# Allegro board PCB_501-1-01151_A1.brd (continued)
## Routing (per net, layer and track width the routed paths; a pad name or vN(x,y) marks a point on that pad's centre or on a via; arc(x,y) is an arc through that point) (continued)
N20248573: length 1.7
  TOP w0.142: U4.A1 90.69,22.51 90.54,22.37 R34.1
N20257520: length 3.2
  TOP w0.142: U7.L9 87.64,38.01 R62.1
N20264538: length 18.6
  TOP w0.381: FB16.2 95.78,26.01 96.42,26.65 v1(97.52,26.65)
  BOTTOM w0.381: v1(97.52,26.65) J2.COM2 97.52,22.25 96.81,21.54 96.81,13.27 98.26,11.82 J2.COM1
N20269907: length 2.6
  TOP w0.142: R803.2 R17.2 57.02,59.46 56.85,59.63 U2.4
N20274074: length 3.3
  TOP w0.142: J8.5 6.61,38.96 FB5.1
N20274097: length 3.1
  TOP w0.142: J8.4 6.49,39.61 7.49,38.61 R173.1
N20280334: length 1.5
  TOP w0.142: D10.2 23.46,41.33 23.26,41.13 R176.2
N20280345: length 1.5
  TOP w0.142: R177.2 8.11,46.34 8.27,46.49 D11.2
N20323615: length 3.7
  BOTTOM w0.142: R133.1 R130.1 55.24,14.24 54.64,14.84 Y1.1
N20326291: length 3.5
  TOP w0.381: R116.2 14.35,34.24 J3.32
N20327026: length 1.4
  TOP w0.203: R109.2 32.78,11.95 D7.2
N20327568: length 5.8
  BOTTOM w0.381: R131.2 17.78,9.52 16.41,8.16 J3.28
N20327935: length 1.1
  TOP w0.142: R124.2 32.9,34.26 D8.2
N20368037: length 5.5
  TOP w0.142: J7.5 6.1,22.2 6.46,21.83 6.46,18.54 FB15.2
N20387129: length 4.1
  BOTTOM w0.142: SW6.5 73.88,16.38 73.9,16.4 R225.1
N20387131: length 8.3
  BOTTOM w0.142: R226.1 78.49,17.02 78.29,17.22 75.64,17.22 75.33,17.53 72.29,17.53 72.01,17.24 SW6.6
N20387133: length 11
  BOTTOM w0.142: R227.1 79.63,17.22 79.29,17.56 75.78,17.56 75.15,18.2 72.3,18.2 70.74,16.64 SW6.7
N20387143: length 13.9
  BOTTOM w0.142: R232.1 80.77,16.89 80.01,17.65 79.69,17.65 79.43,17.91 75.95,17.91 75.31,18.54 70.74,18.54 69.47,17.27 SW6.8
N20387145: length 4.8
  BOTTOM w0.142: SW7.4 91.95,32.13 93.73,30.35 R575.2
N20387147: length 2.9
  BOTTOM w0.142: SW7.3 93.22,32.38 94.11,31.5 R576.2
N20429331: length 3.5
  TOP w0.142: R771.1 92.18,86.47 92.25,86.4 U27.4 93.08,85.2 93.34,84.93 D28.1
N20436944: length 17.8
  BOTTOM w0.381: R121.2 15.46,21.6 J3.9 J3.10 18.49,17.78 J3.4 J3.3 J3.2 J3.1 12.46,17.81 J3.8
N20467513: length 4.5
  TOP w0.142: R579.1 R578.2 93.2,79.64 93.06,79.5 91.84,79.5 91.69,79.64 U26.5
N20496187: length 21.3
  TOP w0.381: R135.2 24.51,35.18 25.78,33.91 25.78,31.49 J3.26
  BOTTOM w0.381: J3.20 J3.19 J3.18 J3.17 18.49,28.22 J3.24 J3.25 J3.26
N20630241: length 5.5
  TOP w0.254: DA8.3 25.82,53 25.4,52.58 24.13,52.58 23.62,53.09 R782.2
N20681531: length 5.8
  TOP w0.142: v1(34.8,18.92) 35.14,18.59 35.37,18.59 C591.2 R810.1 v1(34.8,17.02)
  BOTTOM w0.142: R791.1 34.65,16.87 v1(34.8,17.02) ; v1(34.8,18.92) 34.14,19.58 R790.2
N20684634: length 6.1
  TOP w0.142: v1(35.19,13.42) 35.77,14.01 C592.2 R811.1 35.24,15.43 v1(34.8,15.88)
  BOTTOM w0.142: R793.1 34.7,12.93 v1(35.19,13.42) ; R792.2 34.56,15.64 v1(34.8,15.88)
N20685468: length 5.9
  TOP w0.142: v1(34.56,26.07) 35.19,25.43 R812.1 C593.2 35.21,24.29 v1(34.54,23.62)
  BOTTOM w0.142: v1(34.54,23.62) 34.44,23.73 R794.2 ; v1(34.56,26.07) 34.19,26.44 R795.1
N20685796: length 6.5
  TOP w0.142: v1(34.54,27.05) 35.08,27.05 35.41,27.39 R813.1 C594.2 35.41,29.64 35.08,29.97 v1(34.54,29.97)
  BOTTOM w0.142: R797.1 34.4,30.12 v1(34.54,29.97) ; R796.2 34.18,27.41 v1(34.54,27.05)
N20829804: length 1.3
  TOP w0.142: D29.1 13.52,69.48 13.51,69.47 R266.2
N20866761: length 3.6
  TOP w0.381: J3.33 22.73,34.34 R120.1
N20868982: length 4.5
  BOTTOM w0.381: R134.2 19.68,10.87 J3.29

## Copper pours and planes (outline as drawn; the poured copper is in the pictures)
5VIN on TOP: 22.48,92.33 23.11,91.69 23.11,88.01 24.13,87 24.13,83.57 23.62,83.06 22.61,83.06 22.35,82.8 22.35,82.42 22.31,82.38 21.17,82.38 21.13,82.35 17.6,82.35 17.4,82.55 17.4,92.33
GND on TOP: 27.97,43.59 32.79,43.59 34.5,41.88 34.5,41.36 34.42,41.27 31.37,41.27 31.24,41.4 31.24,41.78 30.73,42.29 28.83,42.29 28.7,42.16 28.7,41.4 28.58,41.27 27.69,41.27 27.05,41.91 27.05,42.67
GND on TOP: 78.87,58.67 78.49,58.29 78.49,56.9 79.12,56.26 79.88,56.26 80.01,56.39 80.01,58.13 80,58.13 79.46,58.67
GND on TOP: 38.35,63.25 39.5,63.25 39.5,62.48 39.37,62.36 38.61,62.36 38.23,62.74 38.23,63.12
GND on TOP: 36.83,60.58 39.37,60.58 39.37,61.21 38.35,61.21 38.23,61.34 38.23,61.47 37.72,61.98 36.96,61.98 36.58,61.6 36.58,60.83
GND on TOP: 77.34,58.29 75.56,58.29 75.18,57.91 75.18,56.77 75.69,56.26 77.34,56.26 77.47,56.39 77.47,58.17
GND on BOTTOM: 1.27,52.36 1.27,1.14 54.13,1.14 54.13,52.36 ; 41 cut-outs
GND on BOTTOM: 1.14,54.53 1.14,79.88 1.02,79.88 1.02,92.46 1.14,92.46 1.14,94.11 98.86,94.11 98.86,54.53 ; 19 cut-outs
GND on BOTTOM: 92.84,86.49 93.6,86.49 93.98,86.11 93.98,85.6 93.6,85.22 92.84,85.22 92.71,85.34 92.71,86.36
GND on BOTTOM: 82.91,79.41 83.26,79.05 83.26,78.57 82.98,78.29 82.15,78.29 81.97,78.47 81.97,79.38 81.99,79.41
GND on BOTTOM: 98.85,52.43 98.85,1.14 85.96,1.14 85.96,52.43 ; 8 cut-outs
GND on BOTTOM: 70.71,30.68 70.71,26.37 73.83,26.37 73.83,30.68
GND on L2_GND: 98.86,1.14 1.14,1.14 1.14,98.86 98.86,98.86 ; 2 cut-outs
GND on L3_SIG1, L4_SIG2: 1.02,79.88 1.02,92.46 8.13,92.46 8.13,79.88
GND on L5_PWR: 1.14,79.88 1.14,92.46 8.13,92.46 8.13,79.88
GND on L5_PWR: 1.14,1.14 1.14,44.25 59.87,44.25 60.32,44.7 63.5,44.7 64.01,45.21 64.01,47.12 65.53,48.64 66.44,48.64 70.89,53.09 86.61,53.09 86.74,52.96 90.81,52.96 95.38,48.39 95.38,44.25 98.86,44.25 98.86,1.14 ; 2 cut-outs
VBUS1_FL on BOTTOM: 92.58,85.98 92.58,84.84 92.07,84.84 91.31,85.6 91.19,85.6 90.68,86.11 90.68,86.74 90.81,86.87 91.69,86.87
VBUS2_FL on BOTTOM: 83.4,79.56 83.4,78.54 83.52,78.41 84.41,78.41 84.41,79.05 83.9,79.56
VBUS3_FL on BOTTOM: 60.96,81.15 60.96,80.37 61.04,80.29 61.04,79.29 61,79.25 61,78.34 61.06,78.28 62.27,78.28 62.27,79.11 62.15,79.22 62.15,80.94 61.94,81.15
VBUS4_FL on BOTTOM: 58.01,80.8 58.01,80.14 58.09,80.06 58.09,78.84 58.01,78.77 58.01,78.46 58.6,77.88 59.11,77.88 59.23,78 59.23,79.78 58.69,80.33 58.69,80.58 58.45,80.82 58.04,80.82
VDD_1V0 on TOP: 42.8,67.56 42.8,66.29 42.93,66.17 44.45,66.17 44.58,66.29 44.58,67.44 44.32,67.69 44.32,68.82 44.17,68.98 43.15,68.98 43.05,68.88 43.05,67.82
VDD_1V8 on TOP: 47.88,71.12 47.88,68.58 48.01,68.45 51.18,68.45 51.44,68.71 51.44,70.87 50.93,71.37 48.13,71.37
VDD_1V8 on L3_SIG1: 75.06,64.9 75.06,52.32 88.65,52.32 89.92,51.05 89.92,30.48 87.25,27.81 87.25,24.38 88.26,23.37 91.57,23.37 92.2,24 92.2,53.21 90.04,55.37 78.87,55.37 78.87,64.9
VDD_1V8 on L4_SIG2: 50.93,35.48 57.91,35.48 60.78,38.35 62.55,38.35 62.55,36.96 59.77,34.18 50.93,34.18
VDD_1V8 on L4_SIG2: 64.39,29.08 67.56,29.08 69.09,27.56 91.19,27.56 92.46,26.29 92.46,21.34 92.07,20.96 90.68,20.96 90.04,21.59 90.04,22.35 89.41,22.99 84.58,22.99 83.19,21.59 74.17,21.59 72.59,23.17 68.13,23.17 66.55,21.59 64.77,21.59 64.13,22.23 64.13,28.83
VDD_1V8 on L5_PWR: 46.3,71.63 76.84,71.63 77.72,70.74 77.72,61.98 77.34,61.6 55.24,61.6 54.61,62.23 54.61,65.81 51.84,68.58 46.1,68.58 46.1,71.42
VDD_1V8_SNS on TOP: 45.36,61.47 45.58,61.47 45.63,61.52 45.63,62.48 45.65,62.55 45.65,63.16 47.5,65 47.5,70.1 47.12,70.49 45.72,70.49 45.15,69.92 45.15,63.86 45.15,63.86 45.15,63.41 45.15,63.4 45.15,62.7 45.32,62.53 45.32,61.51
VDD_COINCELL_IN on BOTTOM: 16.26,75.56 17.91,75.56 18.16,75.31 18.16,73.66 17.27,73.66 16.26,74.68
VDD_DCDC6 on TOP: 39.37,68.83 39.75,68.45 39.75,66.93 39.88,66.8 41.47,66.8 41.69,66.58 41.69,65.45 41.51,65.28 39.88,65.28 39.5,65.66 37.97,65.66 37.72,65.91 37.72,68.33 38.23,68.83
VDD_DCJACK_5VIN on TOP: 8.76,81.79 9.02,81.53 16.38,81.53 16.89,82.04 16.89,91.62 16.44,92.07 9.12,92.07 8.76,91.72
VDD_DCJACK_5VIN on BOTTOM: 8.51,82.3 9.27,81.53 16.38,81.53 16.89,82.04 16.89,92.07 16.51,92.46 9.27,92.46 8.51,91.69
VDD_DCJACK_5VIN on L3_SIG1, L4_SIG2, L5_PWR: 8.76,81.79 9.02,81.53 16.38,81.53 16.89,82.04 16.89,92.07 16.51,92.46 9.02,92.46 8.76,92.2
VDD_EXT_LS_5V0 on TOP: 32.64,91.31 32.64,85.98 34.04,84.58 37.08,84.58 37.34,84.84 37.34,91.31 36.96,91.69 33.02,91.69
VDD_EXT_LS_5V0 on BOTTOM: 33.66,91.44 36.96,91.44 37.34,91.06 37.34,85.34 37.08,85.09 33.91,85.09 33.4,85.6 33.4,91.19
VDD_EXT_LS_5V0 on L5_PWR: 18.26,85.47 18.26,97.26 97.43,97.26 97.43,61.62 96.77,60.96 96.77,56.9 92.33,56.9 89.03,60.2 85.57,60.2 83.54,62.23 80.42,62.23 79.25,63.4 79.25,71.68 78.28,72.64 47.02,72.64 46.08,73.58 46.08,84.73 45.34,85.47
VDD_EXT_LS_5V0_SNS on TOP: 32.89,83.82 33.91,83.82 34.16,84.07 36.7,84.07 37.21,83.57 37.21,80.52 36.96,80.26 32.64,80.26 32.26,80.65 32.26,82.55 32.38,82.68 32.51,82.68 32.64,82.8 32.64,83.57
VDD_HIGH_CAP on L5_PWR: 63.37,47.12 63.37,45.34 63.12,45.09 62.1,45.09 61.72,45.47 61.72,45.85 61.21,46.35 55.63,46.35 55.5,46.48 55.5,47.24 55.75,47.5 62.99,47.5
VDD_HIGH_IN_3V3 on TOP: 46.6,58.45 48.4,58.45 48.59,58.27 48.62,58.23 49.01,58.23 49.09,58.15 49.09,57.77 48.98,57.66 48.52,57.66 47.97,58.21 46.61,58.21 46.6,58.22
VDD_HIGH_IN_3V3 on TOP: 39.88,46.99 40.39,46.48 40.39,42.55 36.83,38.99 34.29,38.99 33.63,39.64 30.59,39.64 30.48,39.75 30.48,40.89 30.35,41.02 29.84,41.02 29.84,41.4 29.97,41.53 30.73,41.53 30.86,41.4 30.86,41.15 30.99,41.02 34.36,41.02 36.58,43.23 36.58,45.59 36.2,45.97 35.05,45.97 34.34,46.69 34.34,47.96 33.4,48.9 30.86,48.9 28.19,51.56 28.19,59.56 28.58,59.94 29.84,59.94 30.35,59.44 30.35,53.59 31.62,52.32 33.35,52.32 35.92,49.76 35.92,48.29 37.21,46.99
VDD_HIGH_IN_3V3 on TOP: 39.59,59.28 39.83,59.28 39.99,59.11 40.25,59.11 40.52,58.84 41.52,58.84 41.53,58.83 41.53,58.63 41.52,58.63 40.41,58.63 40.26,58.77 40.1,58.77 40.1,58.77 39.57,58.77 39.47,58.87 39.47,59.17
VDD_HIGH_IN_3V3 on L3_SIG1: 39.24,57.66 39.5,57.4 48.77,57.4 52.83,61.47 52.83,67.18 51.82,68.2 45.34,68.2 39.88,62.74 28.32,62.74 27.43,61.85 27.43,58.42 28.19,57.66 ; 1 cut-out
VDD_HIGH_IN_3V3 on L4_SIG2: 54.61,44.96 56.77,44.96 57.02,45.21 57.02,45.85 56.77,46.1 56.01,46.1 55.88,45.97 50.67,45.97 49.91,46.74 42.55,46.74 41.4,45.59 37.72,45.59 37.47,45.34 37.47,40.13 35.56,38.23 35.56,20.32 42.86,13.02 59.63,13.02 62.79,9.86 86.18,9.86 89.92,13.59 89.92,21.97 89.28,22.61 85.47,22.61 84.91,22.05 84.91,16.08 82.17,13.34 66.27,13.34 62,17.6 46.66,17.6 39.12,25.15 39.12,37.08 40.39,38.35 40.39,42.55 43.05,45.21 49.66,45.21 50.04,44.83 54.48,44.83
VDD_HIGH_IN_3V3 on L5_PWR: 36.96,45.47 39.86,45.47 39.86,38.99 30.48,38.99 30.48,42.67 36.2,42.67 36.58,43.05 36.58,45.09
VDD_HIGH_IN_3V3_SNS on TOP: 41.4,50.55 40.26,49.4 40.26,47.62 40.13,47.5 37.47,47.5 37.34,47.62 37.34,52.2 37.97,52.83 41.15,52.83 41.4,52.58
VDD_HUB_LED on BOTTOM: 34.36,98.4 88.99,98.4 89.15,98.24 89.15,96.39 89.03,96.27 34.16,96.27 33.91,96.52 33.91,97.95
VDD_LDO1 on TOP: 46.61,58.04 47.94,58.04 48.44,57.54 51.82,57.54 52.44,58.17 53.34,58.17 53.34,56.77 53.21,56.64 52.32,56.64 52.07,56.9 50.16,56.9 50.09,56.82 48.61,56.82 47.61,57.82 46.61,57.82 46.6,57.83 46.6,58.02
VDD_LDO_2V8 on TOP: 54.36,59.44 55.5,59.44 55.75,59.18 55.75,55.75 55.5,55.5 54.23,55.5 53.85,55.88 53.85,58.93
VDD_LDO_2V8 on L4_SIG2: 94.23,55.5 95.57,54.17 95.57,50.61 96.39,49.78 96.39,13.97 89.81,7.39 79.45,7.39 79.45,9.37 86.59,9.37 92.96,15.75 92.96,46.86 87.76,52.07 64.77,52.07 59.44,57.4 54.61,57.4 54.1,57.91 54.1,59.18 54.99,60.07 62.87,60.07 66.68,56.26 77.85,56.26 78.74,55.37 85.98,55.37 86.11,55.5
VDD_NVCC_3V3 on TOP: 41.52,59.24 40.79,59.24 40.78,59.25 40.7,59.25 40.7,59.35 40.44,59.61 40.42,59.61 39.7,60.33 36.2,60.33 36.07,60.2 36.07,59.8 36.2,59.66 39.64,59.66 40,59.3 40.21,59.3 40.49,59.03 40.49,59.03 41.53,59.03 41.53,59.24
VDD_NVCC_3V3 on L4_SIG2: 20.45,46.74 19.3,47.88 19.3,49.78 22.48,49.78 22.48,56.9 26.29,60.71 37.85,60.71 37.85,56.77 27.3,56.77 25.53,54.99 25.53,49.78 26.92,49.78 27.18,49.53 27.18,48.77 25.15,46.74
VDD_NVCC_3V3 on L5_PWR: 57.15,38.99 57.15,45.59 56.9,45.85 48.39,45.85 46.61,47.62 33.66,47.62 30.23,51.05 23.75,51.05 22.73,50.04 22.73,46.23 25.15,43.81 34.04,43.81 36.07,45.85 40.64,45.85 40.77,45.72 40.77,38.34 48.93,38.42 50.38,39.87 55.7,39.87 56.28,39.29 56.28,38.84 56.41,38.71 56.87,38.71
VDD_NVCC_SD1 on TOP: 90.93,23.75 92.33,23.75 93.73,25.15 93.73,30.91 91.87,32.77 85.85,32.77 85.34,32.26 85.34,31.24 85.6,30.99 91.69,30.99 92.46,30.23 92.46,28.7 92.07,28.32 92.07,26.8 92.46,26.42 92.46,25.27 92.07,24.89 90.93,24.89
VDD_NVCC_SD1 on BOTTOM: 65.79,35.31 66.17,35.31 66.68,35.81 74.04,35.81 76.84,33.02 78.61,33.02 79.38,32.26 85.72,32.26 86.11,31.88 86.11,30.47 83.7,30.47 83.06,31.12 76.58,31.12 73.79,33.91 65.79,33.91 64.64,35.05 64.64,35.18 64.77,35.31 65.66,35.31 65.79,35.18
VDD_PERI_3V3 on TOP: 37.62,9.02 37.62,11.2 38.48,12.07 44.96,12.07 45.34,11.68 45.34,11.05 47.73,11.05 49.53,12.85 49.53,17.14 49.66,17.27 51.44,17.27 51.56,17.4 51.56,18.03 51.31,18.29 49.91,18.29 49.66,18.03 48.51,18.03 48.51,18.8 49.15,19.43 51.94,19.43 53.09,20.57 53.09,26.03 53.85,26.8 54.99,26.8 55.24,26.54 55.24,13.97 54.23,12.95 54.23,10.41 53.72,9.91 51.33,9.91 49.71,8.28 38.35,8.28
VDD_PERI_3V3 on TOP: 28.7,41.15 27.18,41.15 26.92,40.89 26.92,38.99 27.18,38.73 28.7,38.73 28.96,38.99 28.96,39.75 29.21,40.01 29.21,40.89 29.34,41.02 29.59,41.02 29.72,41.15 29.72,41.4 29.59,41.53 29.08,41.53
VDD_PERI_3V3 on TOP: 80.14,61.47 80.14,58.65 80.31,58.47 80.31,56.47 80.39,56.39 81.79,56.39 82.55,57.15 82.55,60.96 81.79,61.72 80.39,61.72
VDD_PERI_3V3 on L3_SIG1: 7.11,47.7 7.11,36.91 8.2,35.81 21.21,35.81 22.73,37.34 22.73,39.12 23.5,39.88 27.3,39.88 28.45,38.73 32.26,38.73 34.04,40.51 34.04,45.59 31.75,47.88 28.45,47.88 26.54,45.97 21.84,45.97 20.45,47.37 18.92,47.37 15.24,43.69 10.16,43.69 9.65,44.2 9.65,47.62 9.32,47.96 7.37,47.96
VDD_PERI_3V3 on L3_SIG1: 15.88,14.86 25.53,14.86 26.16,15.49 26.16,21.21 25.27,22.1 19.05,22.1 18.67,22.48 18.67,24.77 19.43,25.53 31.24,25.53 32,26.29 32,30.73 35.05,33.78 39.24,33.78 39.88,34.42 41.58,34.42 41.81,34.19 41.81,33.45 39.53,33.45 39.53,22.31 42.46,22.31 44.32,20.45 44.32,18.97 41.4,16.05 41.4,9.14 40.77,8.51 33.27,8.51 32.51,9.27 32.51,11.68 31.37,12.83 23.37,12.83 21.59,11.05 15.82,11.05 15.49,11.38 15.49,14.48
VDD_PERI_3V3 on L3_SIG1: 32.13,72.01 30.35,72.01 29.21,73.15 15.88,73.15 15.16,72.44 15.16,70.61 26.29,70.61 29.21,67.69 33.15,67.69 33.53,68.07 33.53,70.61
VDD_PERI_3V3 on L3_SIG1: 54.28,1.14 51.66,3.76 51.66,20.24 52.32,20.9 52.32,24.64 54.48,26.8 55.91,26.8 57.02,25.68 57.02,20.07 59.18,17.91 61.98,17.91 62.1,18.03 64.39,18.03 65.28,17.14 65.28,14.48 64.01,13.21 55.5,13.21 53.98,11.68 53.98,7.75 55.88,5.84 57.53,5.84 57.53,5.85 78.28,5.85 82.3,9.87 82.3,15.37 79.5,18.16 79.5,23.11 78.99,23.62 76.33,23.62 76.2,23.75 76.2,26.29 76.33,26.42 84.58,26.42 85.09,25.91 85.09,19.56 85.72,18.92 91.82,18.92 93.41,20.51 93.41,56.77 83.69,56.77 82.93,56.01 80.39,56.01 79.88,56.52 79.88,65.02 80.52,65.66 89.66,65.66 93.73,69.72 93.73,87.27 87.91,93.09 85.17,93.09 84.84,93.42 84.84,96.01 85.09,96.27 91.31,96.27 96.77,90.81 96.77,16.76 95.94,15.93 87.12,15.93 85.85,14.66 85.85,5.62 81.38,1.14
VDD_PERI_3V3 on L4_SIG2: 41.4,34.42 49.78,34.42 51.56,32.64 51.56,28.45 50.93,27.81 42.16,27.81 40.89,29.08 40.89,33.91
VDD_PERI_3V3 on L4_SIG2: 20.07,41.66 34.36,41.66 35.27,40.75 35.27,30.48 32.57,30.48 32.57,35.37 32.58,35.37 32.58,36.9 33.02,37.34 33.02,37.97 32.64,38.35 29.34,38.35 27.3,36.32 20.32,36.32 19.43,37.21 19.43,41.02
VDD_PERI_3V3 on L5_PWR: 16.71,79.06 2.96,79.06 2.16,78.26 2.16,44.65 2.24,44.58 6.35,44.58 6.86,44.07 6.86,32.26 8,31.12 10.54,31.12 12.07,32.64 23.24,32.64 25.27,34.67 25.27,37.11 26.8,38.63 28.73,38.63 29.49,39.4 29.49,42.47 28.78,43.18 24.77,43.18 22.48,45.47 22.48,49.15 20.19,51.44 17.91,51.44 17.08,52.26 17.08,57.21 17.14,57.28 17.14,78.62
VDD_PERI_FIL_3V3 on TOP: 78.99,61.85 75.82,61.85 75.31,61.34 75.31,59.44 75.95,58.8 77.72,58.8 77.98,59.05 79.12,59.05 79.12,61.72
VDD_PERI_FIL_3V3 on BOTTOM: 74.32,65.28 75.06,66.01 75.06,69.98 75.18,70.1 75.18,72.9 74.8,73.28 74.8,73.91 74.55,74.17 73.03,74.17 72.77,73.91 72.77,73.53 72.64,73.41 67.56,73.41 66.68,74.29 66.68,77.47 67.31,78.1 78.36,78.1 81.22,75.25 81.22,63.31 75.56,57.66 65.15,57.66 59.69,63.12 59.69,72.52 60.45,73.28 65.41,73.28 66.55,72.14 66.55,65.66 66.93,65.28
VDD_PMIC_LS_5V0 on TOP: 31.12,58.29 31.12,53.85 31.5,53.47 32.51,53.47 32.89,53.85 32.89,56.01 32.64,56.26 32.64,58.04 32.38,58.29
VDD_PMIC_LS_5V0 on TOP: 58.8,57.91 59.05,57.66 59.94,57.66 60.2,57.91 60.2,59.44 60.07,59.56 58.93,59.56 58.8,59.44
VDD_PMIC_LS_5V0 on BOTTOM: 88.14,60.96 89.03,60.96 89.15,60.83 89.15,59.56 90.04,58.67 90.04,56.39 88.52,56.39 87.88,57.02 87.88,60.71
VDD_PMIC_LS_5V0 on BOTTOM: 33.02,90.68 33.02,87.38 32,87.38 31.62,87.76 29.34,87.76 25.53,83.95 25.53,69.98 33.15,62.36 33.15,54.86 32.51,54.23 30.86,54.23 30.23,54.86 30.23,60.83 23.24,67.82 23.24,87 26.92,90.68
VDD_PMIC_LS_5V0 on L5_PWR: 30.18,56.8 32.99,56.8 36.07,53.72 46.86,53.72 50.55,57.4 53.47,57.4 56.39,60.32 84.2,60.32 85.09,59.44 88.39,59.44 89.66,58.17 89.66,53.34 71.12,53.34 67.82,50.04 67.56,50.04 66.42,48.9 59.94,48.9 58.55,50.29 53.47,50.29 51.94,48.77 49.4,48.77 48.77,49.4 46.99,49.4 46.99,49.28 45.85,48.13 33.66,48.13 29.84,51.94 29.84,56.46
VDD_PMIC_LS_5V0_SNS on TOP: 48.51,59.94 51.44,59.94 51.94,59.44 51.94,58.04 51.73,57.83 50.12,57.83 49.78,58.17 49.78,58.93 49.66,59.05 48.21,59.05 48.18,59.03 46.61,59.03 46.61,59.23 47.8,59.23
VDD_PMIC_LS_5V0_SNS on TOP: 40.39,58.04 41.53,58.04 41.53,57.79 41.01,57.79 40.96,57.74 40.67,57.74 40.6,57.66 40.6,57.57 39.54,56.52 33.15,56.52 33.15,58.04 34.54,58.04 34.67,57.91 37.21,57.91 37.34,57.79 40.13,57.79
VDD_PMIC_LS_5V0_SNS on BOTTOM: 34.54,57.91 36.32,57.91 36.7,57.53 36.7,54.99 40.26,51.44 47.5,51.44 50.8,54.74 50.8,57.4 50.55,57.66 50.55,58.55 50.67,58.67 51.69,58.67 52.2,58.17 52.2,52.7 49.53,50.04 45.85,50.04 45.4,49.59 37.53,49.59 34.29,52.83 34.29,57.66
VDD_SNVS_IN on TOP: 36.32,45.47 36.32,43.18 36.2,43.05 33.91,43.05 33.4,43.56 33.4,44.83 34.29,45.72 36.07,45.72
VDD_SNVS_IN on TOP: 35.94,68.96 37.21,68.96 37.47,68.71 37.47,67.44 37.59,67.31 37.59,66.29 37.47,66.17 35.81,66.17 35.69,66.29 35.69,68.71
VDD_SNVS_IN on L3_SIG1: 19.05,69.34 23.9,69.34 26.42,66.83 34.06,66.83 39.12,71.88 55.88,71.88 57.15,70.61 57.15,64.64 58.42,63.37 58.42,61.34 58.17,61.09 54.61,61.09 53.47,62.23 53.47,67.94 52.7,68.71 45.09,68.71 40.26,63.88 19.43,63.88 18.41,64.9 18.41,68.71
VDD_SNVS_IN on L4_SIG2: 37.08,45.59 37.47,45.97 40.77,45.97 41.91,47.12 48.51,47.12 48.77,47.37 53.34,47.37 53.72,46.99 56.01,46.99 57.15,45.85 57.53,45.85 57.79,46.1 57.79,46.99 55.6,49.17 55.24,49.15 43.31,49.15 42.29,48.13 36.05,48.13 35.05,47.13 34.18,47.13 32.04,44.99 11.78,44.99 9.65,47.12 9.65,60.13 13.53,64.01 22.23,64.01 25.4,67.18 25.4,72.14 20.57,76.96 15.11,76.96 6.98,68.83 6.98,47.88 6.1,46.99 6.1,41.27 8.26,39.12 15.85,39.12 18.65,41.91 36.2,41.91 37.08,42.8
VDD_SOC_ARM_IN on TOP: 52.45,48.01 52.45,45.97 51.94,45.47 49.66,45.47 49.28,45.85 49.28,46.61 49.78,47.12 49.78,48.51 49.91,48.64 51.82,48.64
VDD_SOC_ARM_IN on BOTTOM: 59.05,40.01 60.66,40.01 60.89,40.23 60.89,43.05 61.16,43.33 61.16,43.74 60.83,44.07 59.31,44.07 58.8,43.56 52.35,43.56 51.86,44.04 51.86,45.89 52.45,46.48 52.45,47.24 49.66,47.24 49.53,47.12 49.53,44.07 49.91,43.69 49.91,41.78 50.04,41.66 56.77,41.66 57.79,40.64 58.42,40.64
VDD_SOC_ARM_IN_SNS on TOP: 49.53,49.02 49.53,51.94 49.59,52 49.59,52.8 49.45,52.94 47.41,52.94 47.01,52.55 47.01,47.83 47.71,47.13 49.28,47.13 49.28,48.77
VDD_SOC_CAP on L3_SIG1: 57.91,44.45 61.6,44.45 61.98,44.07 61.98,39.88 61.6,39.5 58.04,39.5 57.91,39.62
VIN_PMIC_5V0 on TOP: 48.08,58.87 48.08,58.88 48.28,58.88 48.34,58.94 49.56,58.94 49.66,58.84 49.66,58.49 49.52,58.36 48.65,58.36 48.38,58.63 46.61,58.63 46.61,58.87
VIN_PMIC_5V0 on TOP: 40.24,58.16 40.62,58.16 40.68,58.21 41.54,58.21 41.54,58.45 40.67,58.45 40.57,58.55 40.34,58.55 40.25,58.63 39.42,58.63 39.36,58.7 39.36,59.15 39.18,59.33 38.87,59.33 38.86,59.32 38.49,59.32 38.35,59.18 38.35,58.17 38.6,57.92 40,57.92
VIN_PMIC_5V0 on TOP: 30.35,76.07 27.56,76.07 26.8,75.31 16.51,75.31 16,75.82 16,79.76 16.13,79.88 19.3,79.88 19.56,80.14 19.56,81.41 20.27,82.12 24.43,82.12 24.77,81.79 27.3,81.79 28.96,83.44 30.86,83.44 30.99,83.57 31.62,83.57 31.62,82.68 32,82.68 32,77.72
VIN_PMIC_5V0 on TOP: 45.09,54.1 45.09,54.84 44.41,55.52 44.41,55.56 44.37,55.6 44.37,56.39 44.37,56.39 44.16,56.39 44.16,55.48 44.16,54.69 44.75,54.1
VIN_PMIC_5V0 on TOP: 40.67,56.9 41.53,56.9 41.66,56.77 41.66,56.64 41.78,56.52 41.91,56.52 41.97,56.46 41.97,55.52 41.82,55.38 40.77,55.38 40.51,55.12 40.01,55.12 39.88,55.24 39.88,55.78 40.65,56.56 40.65,56.88
VIN_PMIC_5V0 on TOP: 46.61,61.02 48.01,61.02 48.06,61.07 48.72,61.07 48.9,61.24 48.9,61.6 48.8,61.69 48.8,61.69 48.7,61.79 47.67,61.79 47.58,61.69 47.58,61.69 47.49,61.6 47.48,61.6 47.14,61.26 46.6,61.26 46.6,61.03
VIN_PMIC_5V0 on TOP: 46.61,56.87 47.58,56.87 48,56.45 48,56.08 47.88,55.96 46.97,55.96 46.82,56.11 46.82,56.34 46.56,56.6 46.56,56.82
VIN_PMIC_5V0 on BOTTOM: 39.85,56.86 39.21,57.5 38.38,57.5 38.23,57.66 38.23,59.31 38.27,59.35 40.29,59.35 40.29,59.33 40.81,58.82 41.8,58.82 42.06,58.56 42.06,56 42.73,55.32 44.43,55.32 44.86,55.75 46.31,55.75 46.46,55.9 46.46,56.37 47.12,57.02 48.26,57.02 48.51,57.28 48.51,58.55 48.13,58.55 47.88,58.8 47.88,60.32 47.62,60.58 46.74,60.58 46.48,60.83 46.48,62.23 46.86,62.61 48.39,62.61 49.15,61.85 49.15,59.31 49.28,59.18 49.91,59.18 50.16,58.93 50.16,54.86 47.5,52.2 40.51,52.2 39.85,52.86
VIN_PMIC_5V0 on L5_PWR: 18.92,83.94 18.92,52.15 19.51,51.56 28.19,51.56 28.58,51.94 28.58,56.38 29.85,57.66 33.21,57.66 36.9,53.98 44.96,53.98 45.34,54.36 46.48,54.36 50.29,58.17 53.34,58.17 54.23,59.05 54.23,64.9 52.07,67.06 44.58,67.06 44.58,82.72 42.9,84.39 19.38,84.39 ; 1 cut-out
(no net) on TOP: 1.14,1.14 1.14,30.18 4.19,30.18 4.19,35.46 1.14,35.46 1.14,65.58 17.83,65.58 17.83,33.02 85.45,33.02 85.45,66.34 1.17,66.34 1.17,79.88 1.14,79.88 1.14,92.46 1.17,92.46 1.17,98.86 34.67,98.86 34.67,96.22 34.51,96.2 34.36,96.24 34.26,96.23 34.21,96.14 34.21,95.76 34.4,95.57 34.67,95.57 34.67,95.89 91.69,95.89 91.69,98.86 98.86,98.86 98.86,32.98 98.82,20.73 98.77,1.14 ; 87 cut-outs
DCDC1_L1 on TOP: 46.1,55.24 46.1,56.39 46.52,56.39 46.52,56.07 46.92,55.67 48.22,55.67 49.48,54.41 49.48,53.67 49.27,53.47 47.5,53.47 47.12,53.85 47.12,54.23
DCDC2_L2 on TOP: 43.38,54.28 43,53.9 43,52.76 43.31,52.45 45.34,52.45 45.59,52.7 45.59,53.59 45.34,53.84 44.8,53.84 44.02,54.62 44.02,55.51 43.97,55.56 43.97,56.4 43.76,56.4 43.76,55.54 43.38,55.15
DCDC3_L3 on TOP: 42.16,55.46 41.97,55.26 40.89,55.26 40.63,55 40.13,55 40.13,55 39.12,55 38.86,54.74 38.86,53.59 39.12,53.34 40.98,53.34 41.62,53.98 41.62,54 42.48,54.86 42.48,55.38 42.39,55.47 42.39,56.39 42.16,56.39
DCDC4_L4A on TOP: 46.16,61.47 46.68,61.47 46.69,61.47 47.1,61.47 47.53,61.9 49.58,61.9 49.58,61.9 49.75,61.9 49.91,62.06 49.91,62.74 49.78,62.87 48.39,62.87 47.73,62.87 47.21,62.34 46.16,62.34 46.16,62.34
DCDC4_L4B on TOP: 45.76,61.46 45.97,61.46 45.97,61.46 45.97,62.39 46.13,62.5 46.83,62.5 47.87,63.55 49.7,63.55 49.86,63.71 49.86,64.44 49.77,64.53 48.84,64.53 48.84,64.52 47.25,64.52 47.24,64.52 47.12,64.52 45.74,63.14 45.74,62.85 45.73,62.81 45.73,61.5
DCDC5_L5 on TOP: 44.45,64.33 43.8,64.33 43.61,64.14 43.61,62.92 43.57,62.88 43.57,61.47 43.37,61.47 43.33,61.51 43.33,62.98 42.7,63.61 42.7,65.44 42.91,65.66 44.45,65.66 44.58,65.53 44.58,64.46
DCDC6_L6 on TOP: 42.16,61.47 42.16,62.36 42.04,62.48 41.15,62.48 40.32,63.32 39.94,63.32 39.76,63.5 39.76,64.78 39.88,64.9 41.53,64.9 41.58,64.85 41.58,63.58 42.42,62.74 42.42,61.47
INT_LDO on TOP: 40.36,57.24 41.52,57.24 41.53,57.23 41.53,57.03 41.51,57 40.62,57 39.09,55.48 38.1,55.48 38.03,55.55 38.03,56.14 38.21,56.32 39.43,56.32
NVCC_DRAM_1V35 on TOP: 46.99,45.21 46.99,43.85 46.32,43.18 43.43,43.18 42.93,43.69 42.93,45.47 43.31,45.85 46.35,45.85
NVCC_DRAM_1V35 on BOTTOM: 62.74,44.83 64.39,44.83 65.15,44.07 66.68,44.07 66.8,43.94 66.8,41.53 67.18,41.15 68.07,41.15 68.2,41.02 68.2,40.26 67.94,40.01 65.66,40.01 65.02,39.37 62.74,39.37 62.61,39.5 62.61,44.7
NVCC_DRAM_1V35 on L4_SIG2: 42.42,44.07 42.42,40.01 43.43,38.99 51.69,38.99 52.2,39.5 70.1,39.5 77.34,32.26 86.61,32.26 88.39,34.04 88.39,45.59 85.98,48.01 74.17,48.01 71.88,45.72 57.79,45.72 56.52,44.45 46.23,44.45 45.85,44.83 43.18,44.83
NVCC_DRAM_1V35_SNS on TOP: 44.96,49.78 45.85,50.67 45.85,51.82 45.59,52.07 43.56,52.07 42.93,51.44 42.93,46.6 43.18,46.35 44.7,46.35 44.96,46.61
NVCC_LCD on TOP: 67.31,15.88 72.9,15.88 74.04,17.02 81.66,17.02 82.55,16.13 82.55,11.18 78.74,7.37 66.73,7.37 66.34,7.75 66.34,14.91 ; 2 cut-outs
NVCC_LCD on L4_SIG2: 44.83,22.61 47.88,22.61 48.26,22.23 48.26,21.72 47.88,21.34 47.88,21.08 48.26,20.7 50.8,20.7 51.31,21.21 59.94,21.21 59.94,18.23 57.33,18.23 57.33,19.32 57.22,19.43 46.61,19.43 44.7,21.34 44.7,22.48
NVCC_LCD on L5_PWR: 55.88,38.48 57.66,38.48 57.66,34.54 57.4,34.29 57.4,22.65 59.62,20.43 59.62,17.04 60.32,16.34 68.58,16.34 68.58,13.7 60.49,13.7 58.2,15.99 58.2,19.53 55.88,21.85
PFBIN on TOP: 46.61,32.26 41.15,32.26 38.1,29.21 38.1,25.02 35.81,22.73 35.81,18.8 42.04,12.57 45.97,12.57 46.1,12.45 46.1,11.43 47.24,11.43 47.37,11.56 47.37,13.84 47.12,14.1 43.56,14.1 40.77,16.89 40.77,19.81 41.02,20.07 42.55,20.07 43.05,20.57 43.05,23.11 42.29,23.88 42.29,29.08 43.87,30.66 46.02,30.66 46.99,31.62 46.99,31.88
PMIC_CC on TOP: 40.6,61.01 41.52,61.01 41.54,61.03 41.54,61.27 41.51,61.31 40.79,61.31 40.55,61.55 40.55,61.94 40.26,62.23 38.35,62.23 37.97,62.61 37.97,63.37 37.85,63.5 35.31,63.5 35.18,63.37 35.18,62.48 35.56,62.1 37.74,62.1 38.36,61.48 39.89,61.48 39.98,61.38 40.23,61.38
SYS_BU on TOP: 39.72,63.2 40.27,63.2 40.42,63.06 40.42,62.7 40.78,62.35 41.97,62.35 42,62.31 42,61.48 41.95,61.43 41.26,61.43 40.22,62.47 39.84,62.47 39.72,62.59

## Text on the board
Ref Des/Assembly Bottom: ASSEMBLY BOT | SHEET 3 OF 3 | LAYER: | REV:A1 | TIXU_MX6Y_Main_Board | 701-1-01380 | DESIGNED FOR: TIXU_MX6Y | PART NO: | PARTNAME: | TOLERANCE + / - 0.1MM | ALL DIMENSIONS ARE IN MM
Package Geometry/Pastemask Bottom: "FIDUCIAL'S  WILL NOT BE THRU OPEN, IT SHOULD BE HALFETCH". | PASTE BOTTOM
Ref Des/Silkscreen Bottom: A | C | D | B | SW6 | 1V35 | 0 | 1 | eMMC | SD | QSPI | P3 | BOOT DEV | P1 | P2 | RESERVED | INTERNAL | SERIAL | P0 | FUSE | ON | BOOT TYPE
User.Comments: PARTNAME: | PART NO: | DESIGNED FOR: TIXU_MX6Y | 501-1-01151 | TIXU_MX6Y_Main_Board | REV:A1 | LAYER: | ALL DIMENSIONS ARE IN MM | TOLERANCE + / - 0.1MM
TOP: L1_TOP
Package Geometry/Pastemask Top: "FIDUCIAL'S  WILL NOT BE THRU OPEN, IT SHOULD BE HALFETCH".
Ref Des/Silkscreen Top: OVP | POR | TX | NVCC_3 | SNVS | PB | PA | P/N:501-1-01151_A1 | SOC | 1V | PG | 2V8 | JTAG | RX | GPIO | 5VIN | H3V3 | 1V8 | BOOT | ON/OFF | RESET | USER_1 | PMIC_PB | USER_2 | USER | P5 | P4 | P3 | P2 | P1 | R
DIMENSION: PARTNAME: | PART NO: | DESIGNED FOR: TIXU_MX6Y | 701-1-01380 | TIXU_MX6Y_Main_Board | REV:A1 | LAYER: | SHEET 2 OF 3 | ASSEMBLY TOP | ALL DIMENSIONS ARE IN MM | TOLERANCE + / - 0.1MM
User.6: T*
User.9: PANEL FIDUCIAL | (TOP AND BOTTOM) | (3 PLACES) | TOOLING HOLES 3.20 MM | (4 PLACES) | MOUSE BITE DETAIL
User.20: PANEL DRAWING BOT | SHEET 3 OF 3 | LAYER: | REV:A1 | TIXU_MX6Y_Main_Board | 501-1-01151 | DESIGNED FOR: TIXU_MX6Y | PART NO: | PARTNAME: | TOLERANCE + / - 0.1MM | ALL DIMENSIONS ARE IN MM
User.21: PARTNAME: | PART NO: | DESIGNED FOR: TIXU_MX6Y | 501-1-01151 | TIXU_MX6Y_Main_Board | REV:A1 | LAYER: | PANEL ART | ALL DIMENSIONS ARE IN MM | TOLERANCE + / - 0.1MM
User.22: DO NOT SCALE DRAWING PRINT | SHEET 1 OF 3 | IMPEDANCE REQUIREMENT | IMPEDANCE TABLE | IMX_6ULL_EVALUATION BOARD
User.23: PMT_ | PMB_ | PNP_ | 501-1-01151_A1 | .ART -  BOTTOM PASTE | .XLS -  PICK AND PLACE DATA | PCB Thickness 1.6 mm | 10) ALL COMPONENT AND MATERIAL USED ARE PB FREE AND ROHS COMPLAINT. | 4) SOLDER PASTE TOOLING SHOULD BE MADE USING PMB_501-1-01151_A1.ART FOR SECONDARY SIDE. | 9) RED COLOR HIGHLIGHTED COMPONENTS ARE NO MOUNT.
User.24: SHEET 1 OF 3 | INITIAL RELEASE
User.25: LAYER STACKUP DETAILS | SOLDER MASK | L1_TOP Cu, 1oz include Plating | 3.66  mil PREPEG | 4 mil, CORE\PREPEG | L2_GND Cu, 1oz | L3_SIG1 Cu, 1oz | 39mil, CORE\PREPEG | L4_SIG2 Cu, 1oz | L5_PWR Cu, 1oz | 3.66 mil PREPEG | L6_BOTTOM Cu, 1oz include Plating | 63 MILS | TOL. +\- 10% | LAYER NAME | L6_BOT | L1_TOP | L3_SIG1 | L4_SIG2 | SINGLE ENDED | 5.6 MILS | WIDTH | 50 OHM | 5 MILS | DIFFERENTIAL 90 OHM | 5.5 MILS | SPACING | 4 MILS | DIFFERENTIAL 100 OHM | 6 MILS | FR-4 Tg 170 Deg C Td 340 Deg C | 19) | 20) | FAB_ | PMT_501-1-01151_A1.ART | SST_ | SMT_ | L6_BOT_ | SSB_ | SMB_ | PNL_ | IPC_ | L2_GND1_ | L3_SIG1_ | L4_SIG2_ | ART_PARAM_ | ART_APER_ | PMB_501-1-01151_A1.ART | L5_PWR _ | NC_TOOLS_ | NC_PARAM_ | RFQ_501-1-01151_A1.XLS | L1_TOP_ | DRL_1-6_ | ROUT_1-6_ | ALL COMPONENT AND MATERIAL USED ARE PB FREE AND ROHS COMPLAINT. | FAB VENDOR SHOULD PROVIDE 5MM BREAKAWAY STRIP ON TWO LONGER(OPPOSITE) SIDES, ALSO | 4NOS OF FIDUCIAL ON TOP SIDE,4NOS OF FIDUCIAL ON BOTTOM SIDE AND 4NOS OF 3.2MM TOOLING HOLES | ARE REQUIRED ON BREAKAWAY STRIP. | 501-1-01151_A1.IPC | 501-1-01151_A1.PDF | 501-1-01151_A1.ART | 501-1-01151_A1.DRL | 501-1-01151_A1.TXT | 501-1-01151_A1.ROUT | -     LAYER 06 (BOTTOM SIDE) | -     LAYER 02 (INNER PLANE 1) | -     SILKSCREEN TOP | -     SOLDERMASK TOP | -     LAYER 05 (INNER PLANE 2) | -     LAYER 03 (INNER SIGNAL1) | -     LAYER 04 (INNER SIGNAL 2) | -     FABRICATION DRAWING | -     PASTEMASK TOP | -     LAYER 01 (TOP SIDE) | -     PASTEMASK BOTTOM | -     SILKSCREEN BOTTOM | -     SOLDERMASK BOTTOM | -     PANEL DRAWING | -     NC DRILL_1-2 | -     NC ROUTE FILE | -     ART PARAMETER | -     ART APERTURE | -     NC TOOLS REPORT | -     NC DRILL PARAMETERS | -     IPC 365 NETLIST | -     FAB RFQ
User.31: PASTE TOP
User.32: SOLDER BOTTOM
User.33: SOLDER TOP
User.34: SILK TOP
User.35: SILK BOTTOM
User.45: PARTNAME: | PART NO: | DESIGNED FOR: TIXU_MX6Y | 501-1-01151 | TIXU_MX6Y_Main_Board | REV:A1 | LAYER: | SHEET 2 OF 3 | PANEL DRAWING TOP | L6_BOT | L3_SIG1 | L4_SIG2 | L2_GND1 | L1_TOP | L5_PWR | ALL DIMENSIONS ARE IN MM | TOLERANCE + / - 0.1MM | FIGURE | FINISHED_SIZE | 8.0 | 35.0 | 36.0 | 40.0 | 53.0 | 62.0 | 87.0 | 91.0 | 126.0 | 30.0 | 63.0 | 130.0 | 47.0x20.0 | 91.0x39.0 | 98.0x39.0 | 118.0x39.0 | DRILL CHART: TOP to BOTTOM | ALL UNITS ARE IN MILS | TOLERANCE_DRILL | +3.0/-3.0 | PLATED | NON-PLATED | QTY | 1517 | 29 | 20 | 8 | 4 | 6 | 5 | 1 | 2 | 1614 | TOTAL HOLES:
